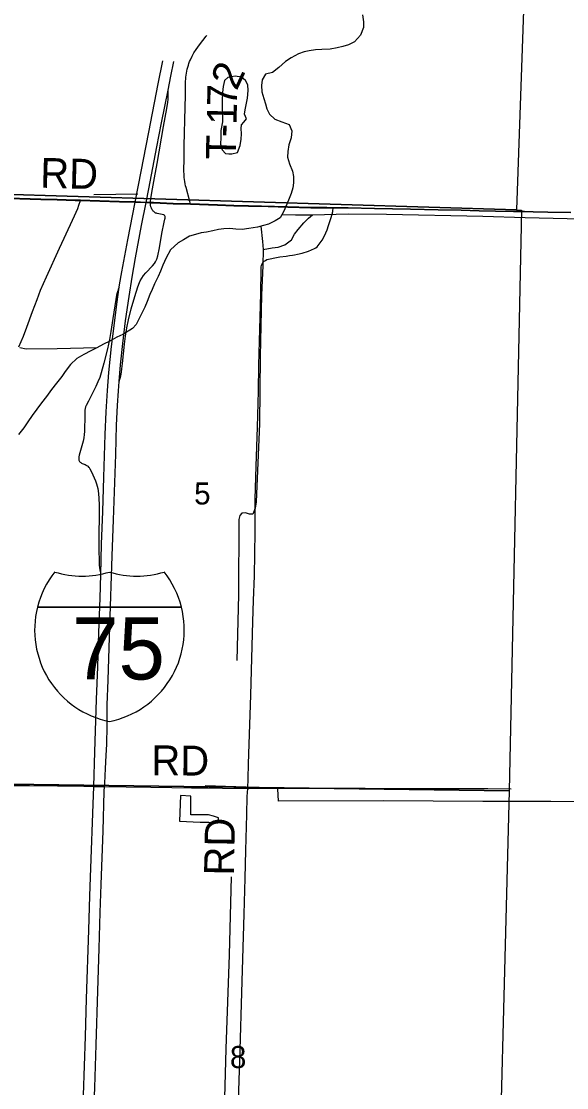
# Model space of a CAD drawing. Extents: x -107 to 120, y -81 to 213.
# Drawn here: x -68.55 to -63.08, y -30.12 to -19.43 of the extents above; entities that cross this region are included whole.
import ezdxf

# ---------------------------------------------------------------- set-up
doc = ezdxf.new("R2010")
doc.units = 0
for name, color, linetype in [('GM_X_Interchange_Ramps', 7, 'Continuous'), ('GM_X_Interstate_Location', 7, 'Continuous'), ('GM_X_Interstate_Route', 7, 'Continuous'), ('GM_X_Interstate_Shield', 7, 'Continuous'), ('GM_X_Major_River', 7, 'Continuous'), ('GM_X_Minor_Lake', 7, 'Continuous'), ('GM_X_Minor_River', 7, 'Continuous'), ('GM_X_Section', 7, 'Continuous'), ('GM_X_Section_Text', 7, 'Continuous'), ('GM_X_Township', 7, 'Continuous'), ('GM_X_Township_Road', 7, 'Continuous'), ('GM_X_Township_Road_Text', 7, 'Continuous')]:
    doc.layers.add(name, color=color, linetype=linetype)

msp = doc.modelspace()

# ---------------------------------------------------------------- linework, layer by layer
at = {"layer": 'GM_X_Interchange_Ramps'}
for points in [[(-67.26, -21.248), (-67.259, -21.238), (-67.255, -21.206), (-67.237, -21.109), (-67.216, -20.997), (-67.191, -20.852), (-67.126, -20.481), (-67.095, -20.303), (-67.09, -20.278), (-67.085, -20.241), (-67.082, -20.209), (-67.08, -20.184), (-67.081, -20.119)], [(-67.572, -23.041), (-67.556, -22.983), (-67.55, -22.946), (-67.544, -22.913), (-67.538, -22.861), (-67.519, -22.665), (-67.508, -22.584), (-67.495, -22.503), (-67.478, -22.423), (-67.45, -22.312), (-67.415, -22.186), (-67.385, -22.092), (-67.368, -22.046), (-67.362, -22.031), (-67.346, -22.002), (-67.327, -21.976), (-67.306, -21.951), (-67.238, -21.88), (-67.217, -21.855), (-67.208, -21.841), (-67.2, -21.827), (-67.194, -21.812), (-67.185, -21.781), (-67.169, -21.7), (-67.144, -21.555), (-67.121, -21.443), (-67.113, -21.411), (-67.112, -21.401), (-67.111, -21.394), (-67.111, -21.39), (-67.112, -21.384), (-67.114, -21.379), (-67.117, -21.375), (-67.119, -21.372), (-67.122, -21.369), (-67.127, -21.367), (-67.142, -21.364), (-67.175, -21.359), (-67.191, -21.356), (-67.199, -21.353), (-67.206, -21.35), (-67.213, -21.345), (-67.219, -21.341), (-67.225, -21.336), (-67.231, -21.33), (-67.236, -21.324), (-67.241, -21.317), (-67.249, -21.302), (-67.255, -21.287), (-67.258, -21.271), (-67.259, -21.259), (-67.26, -21.248)], [(-67.571, -22.093), (-67.578, -22.108), (-67.582, -22.117), (-67.587, -22.13), (-67.592, -22.15), (-67.598, -22.175), (-67.607, -22.217), (-67.635, -22.407), (-67.654, -22.537), (-67.669, -22.618), (-67.69, -22.714), (-67.726, -22.857), (-67.752, -22.952), (-67.767, -22.999), (-67.785, -23.045), (-67.805, -23.09), (-67.881, -23.236), (-67.903, -23.28), (-67.909, -23.295), (-67.913, -23.311), (-67.915, -23.327), (-67.917, -23.36), (-67.918, -23.425), (-67.92, -23.491), (-67.921, -23.54), (-67.922, -23.572), (-67.927, -23.605), (-67.934, -23.637), (-67.974, -23.779), (-67.977, -23.795), (-67.978, -23.812), (-67.978, -23.819), (-67.976, -23.828), (-67.973, -23.835), (-67.969, -23.842), (-67.963, -23.849), (-67.957, -23.854), (-67.95, -23.859), (-67.944, -23.863), (-67.913, -23.874), (-67.903, -23.878), (-67.898, -23.881), (-67.89, -23.887), (-67.885, -23.891), (-67.878, -23.898), (-67.874, -23.903), (-67.865, -23.916), (-67.849, -23.946), (-67.822, -24.005), (-67.81, -24.036), (-67.8, -24.067), (-67.787, -24.115), (-67.779, -24.163), (-67.775, -24.212), (-67.773, -24.278), (-67.776, -24.689), (-67.771, -24.881), (-67.765, -24.93), (-67.757, -24.975)]]:
    msp.add_lwpolyline(points, dxfattribs=at)
at = {"layer": 'GM_X_Interstate_Route'}
for points in [[(-67.571, -22.093), (-67.568, -22.071), (-67.546, -21.941), (-67.485, -21.619), (-67.412, -21.242), (-67.378, -21.071), (-67.274, -20.54), (-67.18, -20.056), (-67.134, -19.824)], [(-67.081, -20.119), (-67.053, -19.979), (-67.024, -19.829)], [(-67.828, -30.449), (-67.817, -30.121), (-67.804, -29.695), (-67.786, -29.153), (-67.772, -28.727), (-67.761, -28.366), (-67.751, -28.087), (-67.733, -27.546), (-67.721, -27.152), (-67.719, -27.103), (-67.717, -27.07), (-67.708, -26.923), (-67.701, -26.792), (-67.697, -26.677), (-67.694, -26.496), (-67.691, -26.283), (-67.684, -26.037), (-67.666, -25.496), (-67.643, -24.79), (-67.63, -24.429), (-67.607, -23.773), (-67.598, -23.478), (-67.59, -23.281), (-67.58, -23.134), (-67.572, -23.041), (-67.557, -22.872), (-67.535, -22.66), (-67.508, -22.431), (-67.473, -22.188), (-67.442, -21.993), (-67.408, -21.799), (-67.347, -21.476), (-67.301, -21.246), (-67.273, -21.106), (-67.194, -20.687), (-67.147, -20.445), (-67.081, -20.119)], [(-67.93, -30.2), (-67.911, -29.61), (-67.899, -29.232), (-67.876, -28.543), (-67.866, -28.199), (-67.855, -27.92), (-67.833, -27.28), (-67.827, -27.101), (-67.816, -26.755), (-67.799, -26.23), (-67.787, -25.902), (-67.776, -25.558), (-67.764, -25.213), (-67.757, -24.975), (-67.748, -24.672), (-67.735, -24.344), (-67.725, -23.999), (-67.711, -23.573), (-67.701, -23.343), (-67.688, -23.13), (-67.674, -22.95), (-67.648, -22.689), (-67.627, -22.51), (-67.595, -22.266), (-67.571, -22.093)]]:
    msp.add_lwpolyline(points, dxfattribs=at)
at = {"layer": 'GM_X_Interstate_Shield'}
for p, q in [((-68.391, -25.302), (-66.948, -25.302)), ((-66.948, -25.302), (-68.391, -25.302)), ((-66.948, -25.302), (-68.391, -25.302))]:
    msp.add_line(p, q, dxfattribs=at)
for centre, start, end in [((-67.482, -25.532), 141.669, 165.8066), ((-67.943, -24.054), 253.0091, 286.9909), ((-67.395, -24.054), 253.0091, 286.9909), ((-67.857, -25.532), 14.1934, 38.331), ((-67.482, -25.532), 165.8066, 258.463), ((-67.857, -25.532), 281.537, 14.1934)]:
    msp.add_arc(centre, 0.938, start, end, dxfattribs=at)
at = {"layer": 'GM_X_Major_River'}
for points in [[(-65.132, -19.361), (-65.123, -19.431), (-65.122, -19.491), (-65.15, -19.565), (-65.213, -19.632), (-65.272, -19.663), (-65.33, -19.68), (-65.387, -19.693), (-65.457, -19.708), (-65.539, -19.711), (-65.602, -19.715), (-65.668, -19.724), (-65.718, -19.735), (-65.775, -19.754), (-65.848, -19.795), (-65.905, -19.832), (-65.97, -19.891), (-66.035, -19.942), (-66.104, -19.959), (-66.139, -20.015), (-66.144, -20.071), (-66.141, -20.133), (-66.122, -20.202), (-66.105, -20.256), (-66.09, -20.306), (-66.063, -20.357), (-66.01, -20.408), (-65.94, -20.435), (-65.868, -20.463), (-65.841, -20.526), (-65.848, -20.596), (-65.87, -20.667), (-65.881, -20.733), (-65.884, -20.789), (-65.865, -20.856), (-65.834, -20.931), (-65.825, -20.983), (-65.824, -21.047), (-65.829, -21.099), (-65.848, -21.153), (-65.867, -21.205), (-65.89, -21.261), (-65.922, -21.332), (-65.957, -21.4), (-66.008, -21.429), (-66.075, -21.462), (-66.125, -21.475), (-66.186, -21.492), (-66.272, -21.507), (-66.338, -21.515), (-66.403, -21.512), (-66.461, -21.507), (-66.523, -21.508), (-66.575, -21.515), (-66.632, -21.528), (-66.696, -21.541), (-66.748, -21.55), (-66.807, -21.565), (-66.865, -21.584), (-66.928, -21.619), (-66.979, -21.648), (-67.057, -21.721), (-67.102, -21.799), (-67.134, -21.874), (-67.157, -21.934), (-67.18, -21.986), (-67.217, -22.059), (-67.242, -22.117), (-67.263, -22.169), (-67.291, -22.237), (-67.314, -22.296), (-67.403, -22.469)], [(-67.403, -22.469), (-67.437, -22.509), (-67.536, -22.568), (-67.596, -22.594), (-67.667, -22.634), (-67.729, -22.667), (-67.795, -22.703), (-67.857, -22.733), (-67.926, -22.769), (-67.998, -22.811), (-68.06, -22.871), (-68.114, -22.941), (-68.147, -22.991), (-68.201, -23.057), (-68.251, -23.121), (-68.3, -23.189), (-68.35, -23.253), (-68.446, -23.381), (-68.487, -23.446), (-68.529, -23.506), (-68.581, -23.572)]]:
    msp.add_lwpolyline(points, dxfattribs=at)
at = {"layer": 'GM_X_Minor_Lake'}
for p, q in [((-66.54, -20.22), (-66.536, -20.435)), ((-66.854, -27.198), (-66.957, -27.192))]:
    msp.add_line(p, q, dxfattribs=at)
for points in [[(-66.536, -20.435), (-66.551, -20.521), (-66.553, -20.593), (-66.554, -20.661), (-66.539, -20.716), (-66.507, -20.752), (-66.473, -20.757), (-66.443, -20.757), (-66.385, -20.744), (-66.357, -20.673), (-66.348, -20.609), (-66.345, -20.555), (-66.35, -20.504), (-66.344, -20.466), (-66.321, -20.439), (-66.294, -20.405), (-66.316, -20.359), (-66.309, -20.315), (-66.285, -20.199), (-66.277, -20.121), (-66.28, -20.064), (-66.306, -20.022), (-66.345, -19.987), (-66.409, -19.978), (-66.482, -19.991), (-66.514, -20.02), (-66.529, -20.082), (-66.534, -20.14), (-66.54, -20.22)], [(-66.957, -27.192), (-66.967, -27.449), (-66.761, -27.461), (-66.671, -27.46), (-66.632, -27.465), (-66.602, -27.465), (-66.574, -27.456), (-66.577, -27.418), (-66.625, -27.401), (-66.677, -27.388), (-66.713, -27.385), (-66.765, -27.386), (-66.852, -27.387), (-66.854, -27.198)]]:
    msp.add_lwpolyline(points, dxfattribs=at)
at = {"layer": 'GM_X_Minor_River'}
for points in [[(-67.384, -21.162), (-67.827, -21.169)], [(-66.127, -21.716), (-66.037, -21.701), (-65.977, -21.694), (-65.912, -21.67), (-65.845, -21.619), (-65.812, -21.563), (-65.777, -21.515), (-65.721, -21.448), (-65.672, -21.403), (-65.632, -21.37)], [(-65.938, -21.364), (-65.802, -21.369), (-65.632, -21.37), (-65.276, -21.36), (-64.891, -21.363), (-63.924, -21.382), (-63.501, -21.394), (-62.939, -21.408), (-62.388, -21.412), (-62.221, -21.421)], [(-66.152, -21.483), (-66.136, -21.635), (-66.127, -21.716), (-66.13, -21.878), (-66.146, -22.173), (-66.157, -22.79), (-66.165, -23.464), (-66.199, -24.246), (-66.208, -24.31), (-66.231, -24.37), (-66.264, -24.371), (-66.305, -24.356), (-66.342, -24.362), (-66.362, -24.383), (-66.371, -24.425), (-66.376, -25.179), (-66.392, -25.837)], [(-67.795, -22.703), (-68.194, -22.712), (-68.504, -22.715), (-68.568, -22.701)], [(-56.985, -27.335), (-57.003, -27.276), (-57.635, -27.273), (-58.808, -27.276), (-59.947, -27.271), (-60.974, -27.264), (-62.22, -27.26), (-63.241, -27.253), (-63.923, -27.253), (-64.92, -27.247), (-65.973, -27.251), (-65.982, -27.125), (-66.299, -27.109), (-66.708, -27.096)], [(-66.576, -32.466), (-66.576, -32.339), (-66.566, -32.153), (-66.548, -31.416), (-66.519, -30.474), (-66.499, -29.734), (-66.465, -28.792), (-66.444, -28.009)]]:
    msp.add_lwpolyline(points, dxfattribs=at)
at = {"layer": 'GM_X_Section'}
for points in [[(-68.686, -15.892), (-63.4, -15.981), (-63.586, -21.317), (-68.865, -21.158), (-69.043, -21.152)], [(-68.865, -21.158), (-63.586, -21.317), (-63.538, -21.32), (-63.66, -27.145), (-68.933, -27.074)], [(-68.933, -27.074), (-63.66, -27.145), (-63.796, -32.429), (-69.123, -32.363)]]:
    msp.add_lwpolyline(points, close=True, dxfattribs=at)
at = {"layer": 'GM_X_Township'}
for points in [[(-63.042, -21.345), (-63.272, -21.342), (-63.42, -21.338), (-63.507, -21.336), (-63.617, -21.335), (-63.797, -21.33), (-63.962, -21.327), (-64.142, -21.322), (-64.372, -21.318), (-64.651, -21.312), (-65.012, -21.304), (-65.275, -21.298), (-65.428, -21.297), (-65.488, -21.296), (-65.652, -21.294), (-65.882, -21.287), (-66.276, -21.278), (-66.423, -21.275), (-66.587, -21.268), (-66.858, -21.259), (-67.03, -21.254), (-67.227, -21.246), (-67.261, -21.245), (-67.302, -21.244), (-67.413, -21.239), (-67.571, -21.235), (-67.768, -21.227), (-67.961, -21.222), (-68.014, -21.22), (-68.194, -21.214), (-68.359, -21.211), (-68.785, -21.198)], [(-68.785, -21.198), (-68.359, -21.211), (-68.194, -21.214), (-68.014, -21.22), (-67.961, -21.222), (-67.768, -21.227), (-67.571, -21.235), (-67.413, -21.239), (-67.302, -21.244), (-67.261, -21.245), (-67.227, -21.246), (-67.03, -21.254), (-66.858, -21.259), (-66.587, -21.268), (-66.423, -21.275), (-66.276, -21.278), (-65.882, -21.287), (-65.652, -21.294), (-65.488, -21.296), (-65.428, -21.297), (-65.275, -21.298), (-65.012, -21.304), (-64.651, -21.312), (-64.372, -21.318), (-64.142, -21.322), (-63.962, -21.327), (-63.797, -21.33), (-63.617, -21.335), (-63.507, -21.336), (-63.42, -21.338), (-63.272, -21.342), (-63.042, -21.345)]]:
    msp.add_lwpolyline(points, dxfattribs=at)
at = {"layer": 'GM_X_Township_Road'}
for points in [[(-66.857, -21.262), (-66.864, -21.235), (-66.901, -21.095), (-66.906, -21.076), (-66.91, -21.057), (-66.914, -21.033), (-66.916, -21.015), (-66.919, -20.994), (-66.92, -20.972), (-66.922, -20.923), (-66.921, -20.808), (-66.919, -20.677), (-66.911, -20.289), (-66.908, -20.171), (-66.908, -20.053), (-66.907, -20.029), (-66.905, -20.007), (-66.903, -19.988), (-66.901, -19.968), (-66.898, -19.949), (-66.894, -19.929), (-66.89, -19.908), (-66.884, -19.888), (-66.878, -19.868), (-66.872, -19.85), (-66.865, -19.83), (-66.858, -19.814), (-66.841, -19.778), (-66.822, -19.744), (-66.8, -19.711), (-66.765, -19.663), (-66.7, -19.576), (-66.694, -19.568)], [(-70.164, -21.153), (-70.145, -21.154), (-69.817, -21.164), (-69.571, -21.172), (-69.44, -21.178), (-69.342, -21.182), (-69.21, -21.186), (-69.128, -21.189), (-68.784, -21.201), (-68.357, -21.213), (-68.304, -21.215)], [(-68.304, -21.215), (-68.193, -21.217), (-68.013, -21.223), (-67.959, -21.224)], [(-68.169, -21.703), (-68.123, -21.602), (-68.02, -21.379), (-67.988, -21.304), (-67.977, -21.273), (-67.959, -21.224)], [(-67.959, -21.224), (-67.767, -21.23), (-67.57, -21.238), (-67.412, -21.242), (-67.301, -21.246), (-67.26, -21.248), (-67.225, -21.249), (-67.029, -21.257), (-66.857, -21.262)], [(-66.857, -21.262), (-66.586, -21.271), (-66.422, -21.278), (-66.274, -21.281), (-66.175, -21.283)], [(-66.175, -21.283), (-65.88, -21.29), (-65.651, -21.297), (-65.487, -21.299), (-65.427, -21.3)], [(-66.282, -27.121), (-66.277, -27.023), (-66.274, -26.875), (-66.269, -26.678), (-66.253, -26.186), (-66.23, -25.449), (-66.223, -25.236), (-66.216, -24.99), (-66.207, -24.547), (-66.208, -24.399), (-66.207, -24.219), (-66.197, -23.891), (-66.185, -23.498), (-66.176, -23.137), (-66.17, -22.875), (-66.15, -22.153), (-66.149, -21.924), (-66.147, -21.891), (-66.144, -21.875), (-66.139, -21.859), (-66.13, -21.845), (-66.118, -21.834), (-66.105, -21.825), (-66.09, -21.818), (-66.058, -21.809), (-66.011, -21.799), (-65.961, -21.791), (-65.897, -21.782), (-65.862, -21.777), (-65.832, -21.772), (-65.812, -21.769), (-65.784, -21.764), (-65.736, -21.752), (-65.673, -21.732), (-65.643, -21.721), (-65.613, -21.707), (-65.599, -21.698), (-65.586, -21.688), (-65.576, -21.677), (-65.565, -21.664), (-65.537, -21.623), (-65.513, -21.58), (-65.499, -21.55), (-65.487, -21.52), (-65.473, -21.477), (-65.449, -21.406), (-65.436, -21.363), (-65.433, -21.353), (-65.431, -21.344), (-65.429, -21.335), (-65.428, -21.328), (-65.427, -21.3)], [(-68.578, -22.691), (-68.532, -22.586), (-68.497, -22.494), (-68.442, -22.339), (-68.396, -22.216), (-68.36, -22.125), (-68.3, -21.99), (-68.169, -21.703)], [(-68.771, -27.088), (-68.634, -27.091), (-68.47, -27.093), (-68.192, -27.097), (-68.028, -27.097), (-67.827, -27.101), (-67.719, -27.103), (-67.502, -27.106), (-67.256, -27.11), (-67.043, -27.112), (-66.846, -27.115), (-66.761, -27.116)], [(-66.761, -27.116), (-66.682, -27.117), (-66.534, -27.118), (-66.282, -27.121)], [(-66.448, -32.366), (-66.449, -32.357), (-66.449, -32.319), (-66.448, -32.255), (-66.443, -32.071), (-66.43, -31.76), (-66.414, -31.285), (-66.397, -30.859), (-66.387, -30.547), (-66.378, -30.318), (-66.373, -30.154), (-66.359, -29.744), (-66.341, -29.17), (-66.318, -28.383), (-66.307, -28.023), (-66.301, -27.744), (-66.293, -27.383), (-66.287, -27.203), (-66.282, -27.121)], [(-66.282, -27.121), (-66.272, -27.122), (-65.697, -27.12), (-65.451, -27.119), (-65.106, -27.12), (-64.811, -27.121), (-64.499, -27.121), (-64.138, -27.122), (-63.875, -27.123), (-63.641, -27.125)]]:
    msp.add_lwpolyline(points, dxfattribs=at)

# ---------------------------------------------------------------- texts
at = {"layer": 'GM_X_Interstate_Location'}
for s in ['.', '-', ',']:
    msp.add_text(s, height=0.001, dxfattribs=at).set_placement((-67.669, -25.701))
msp.add_text('75', height=0.001, rotation=0, dxfattribs=at).set_placement((-67.874, -25.908))
at = {"layer": 'GM_X_Interstate_Shield'}
msp.add_text('75', height=0.625, dxfattribs=at).set_placement((-68.043, -26.029))
at = {"layer": 'GM_X_Section_Text'}
for s, p in [('5', (-66.82, -24.274)), ('8', (-66.461, -29.927))]:
    msp.add_text(s, height=0.221, rotation=0, dxfattribs=at).set_placement(p)
at = {"layer": 'GM_X_Township_Road_Text'}
for s, rotation, p in [('2', 65.0293, (-66.394, -20.131)), ('7', 88.7607, (-66.391, -20.284)), ('1', 88.7521, (-66.395, -20.469)), ('-', 88.7431, (-66.398, -20.592)), ('T', 88.7485, (-66.403, -20.816)), ('RD', 358.5255, (-68.367, -21.096)), ('RD', 359.5061, (-67.25, -26.989)), ('RD', 89.0128, (-66.421, -27.998))]:
    msp.add_text(s, height=0.3, rotation=rotation, dxfattribs=at).set_placement(p)

doc.saveas('drawing.dxf')
